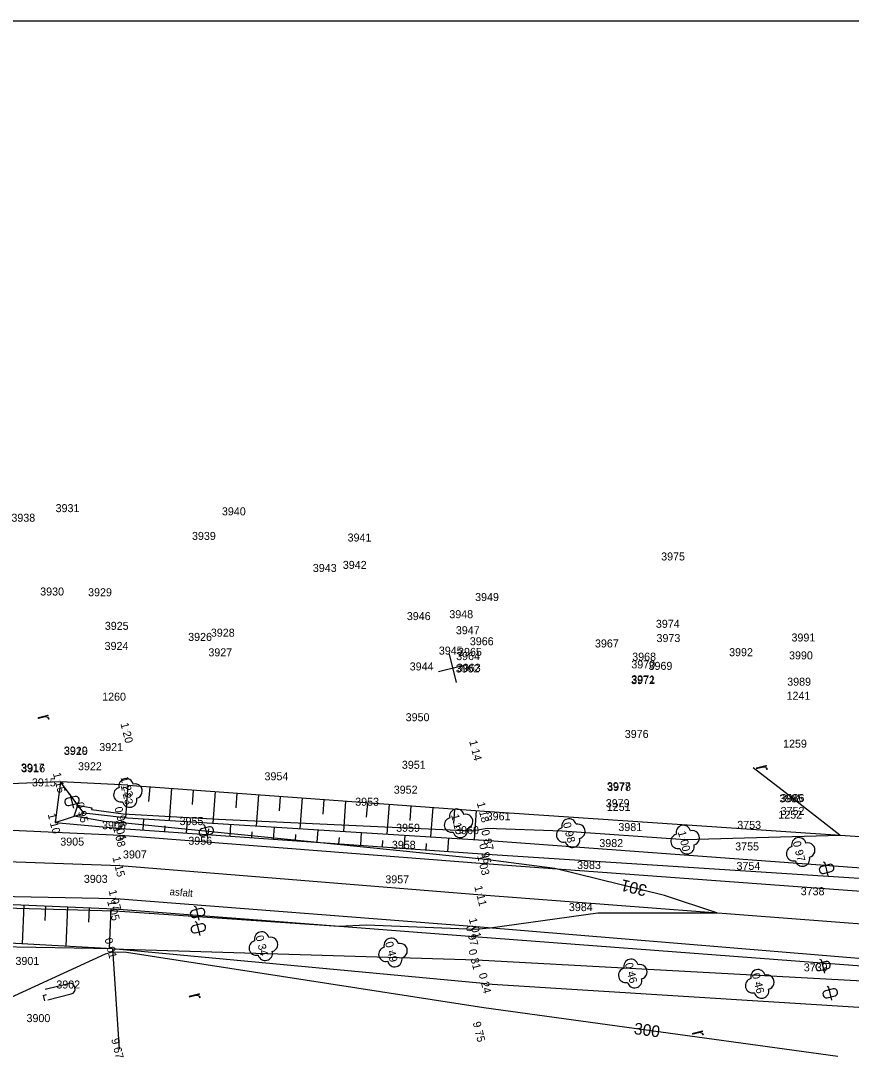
# Model space of a CAD drawing. Extents: x -740053 to -737517, y -1033516 to -1032488.
# Drawn here: x -739360.1 to -739303, y -1032577.7 to -1032506.5 of the extents above; entities that cross this region are included whole.
import ezdxf

# ---------------------------------------------------------------- set-up
doc = ezdxf.new("R2010")
doc.units = 0
for name, color, linetype in [('bod-cislo', 7, 'Continuous'), ('bod-oznac', 7, 'Continuous'), ('bod-vyska', 7, 'Continuous'), ('bod-vyska100', 7, 'Continuous'), ('Contours', 7, 'Continuous'), ('Contours highlighted', 7, 'Continuous'), ('Contours text', 7, 'Continuous'), ('ctv-sit', 7, 'Continuous'), ('Hranice-zelene', 7, 'Continuous'), ('nazvy-bud-povr', 7, 'Continuous'), ('osa-komunikace', 7, 'Continuous'), ('Predmety bez rozlišeni', 7, 'Continuous'), ('silnice', 7, 'Continuous'), ('Technické šrafy', 7, 'Continuous'), ('Terenni-hrana', 7, 'Continuous'), ('Znacky-kultury', 7, 'Continuous')]:
    doc.layers.add(name, color=color, linetype=linetype)

# ---------------------------------------------------------------- blocks, each defined once
blk = doc.blocks.new('POINT_DISPLAY')
blk.add_line((0, 0), (0, 0))
blk = doc.blocks.new('p_strom')
for centre, start, end in [((0, 1), 0, 180), ((-1, 0), 90, 270), ((1, 0), 270, 90), ((0, -1), 180, 0)]:
    blk.add_arc(centre, 1, start, end)
at = {"rotation": -180}
blk.add_blockref('POINT_DISPLAY', (0, 0), dxfattribs=at)
blk = doc.blocks.new('p_orna')
blk.add_text('r', height=2).set_placement((0, 0))
blk = doc.blocks.new('p_leslis')
for p, q in [((-0.05, 4.51), (0.05, 4.51)), ((-0.75, 0.5), (-0.75, 3.81)), ((0.75, 0.5), (0.75, 3.81)), ((0, 0), (0, 0.5)), ((0, 0), (0.75, 0))]:
    blk.add_line(p, q)
for centre, start, end in [((-0.05, 3.81), 90, 180), ((0.05, 3.81), 0, 90)]:
    blk.add_arc(centre, 0.7, start, end)
blk = doc.blocks.new('p_neplod')
for p, q in [((-0.82, 0), (-0.99, -0.18)), ((1, 0), (-0.82, 0)), ((-0.49, 0.56), (-0.49, -0.55)), ((0.05, 1.01), (-0.04, 1.01)), ((0.5, -0.55), (0.5, 0.56)), ((-0.04, -1), (0.05, -1))]:
    blk.add_line(p, q)
for centre, start, end in [((-0.04, 0.56), 90, 180), ((0.05, 0.56), 0, 90), ((-0.04, -0.55), 180, 270), ((0.05, -0.55), 270, 0)]:
    blk.add_arc(centre, 0.45, start, end)
blk = doc.blocks.new('ctvsit')
for p, q in [((0, -2), (0, 2)), ((2, 0), (-2, 0))]:
    blk.add_line(p, q)

msp = doc.modelspace()

# ---------------------------------------------------------------- linework, layer by layer
at = {"layer": 'Contours'}
msp.add_lwpolyline([(-739362.052, -1032567.418), (-739353.659, -1032567.65), (-739352.931, -1032567.699), (-739338.222, -1032568.7), (-739336.341, -1032568.627), (-739328.835, -1032568.904), (-739327.885, -1032568.825), (-739327.83, -1032568.815), (-739320.436, -1032567.79), (-739312.26, -1032567.79), (-739315.844, -1032566.595), (-739323.386, -1032564.753), (-739328.151, -1032564.126), (-739340.621, -1032562.877), (-739353.152, -1032561.618), (-739354.333, -1032561.52), (-739356.417, -1032561.151), (-739356.164, -1032560.396), (-739355.201, -1032560.581), (-739355.221, -1032560.688), (-739353.059, -1032560.997), (-739346.513, -1032561.359), (-739329.091, -1032562.156), (-739328.043, -1032561.983), (-739322.887, -1032562.165), (-739314.427, -1032562.758), (-739303.794, -1032562.445), (-739307.763, -1032559.369), (-739309.748, -1032557.831)], dxfattribs=at)
at = {"layer": 'Contours highlighted'}
msp.add_lwpolyline([(-739403.299, -1032570.496), (-739400.56, -1032570.2), (-739399.624, -1032570.099), (-739390.755, -1032569.573), (-739383.351, -1032569.14), (-739380.871, -1032569.427), (-739380.305, -1032569.493), (-739366.512, -1032571.086), (-739362.044, -1032573.97), (-739361.961, -1032574.147), (-739354.274, -1032570.607), (-739353.782, -1032570.469), (-739352.822, -1032570.487), (-739328.276, -1032574.302), (-739303.936, -1032577.649)], dxfattribs=at)
at = {"layer": 'Hranice-zelene'}
for q in [(-739363.363, -1032570.111), (-739353.338, -1032577.163)]:
    msp.add_line((-739353.795, -1032570.266), q, dxfattribs=at)
at = {"layer": 'osa-komunikace'}
for p, q in [((-739362.629, -1032564.22), (-739353.276, -1032564.547)), ((-739353.276, -1032564.547), (-739328.403, -1032566.555)), ((-739328.403, -1032566.555), (-739297.585, -1032568.913))]:
    msp.add_line(p, q, dxfattribs=at)
at = {"layer": 'Predmety bez rozlišeni'}
for p, q in [((-739409.249, -1032506.478), (-739304.249, -1032506.478)), ((-739304.249, -1032506.478), (-739199.249, -1032506.478))]:
    msp.add_line(p, q, dxfattribs=at)
at = {"layer": 'silnice'}
for p, q in [((-739362.196, -1032562.049), (-739353.246, -1032562.456)), ((-739353.246, -1032562.456), (-739328.225, -1032564.396)), ((-739328.225, -1032564.396), (-739297.577, -1032566.653)), ((-739362.816, -1032566.629), (-739353.554, -1032566.803)), ((-739353.554, -1032566.803), (-739328.793, -1032568.736)), ((-739328.793, -1032568.736), (-739297.981, -1032571.271))]:
    msp.add_line(p, q, dxfattribs=at)
at = {"layer": 'Technické šrafy'}
for p, q in [((-739352.727, -1032559.026), (-739352.89, -1032561.262)), ((-739351.231, -1032559.134), (-739351.304, -1032560.132)), ((-739349.735, -1032559.243), (-739349.896, -1032561.45)), ((-739348.239, -1032559.352), (-739348.312, -1032560.35)), ((-739346.743, -1032559.461), (-739346.902, -1032561.638)), ((-739345.247, -1032559.57), (-739345.32, -1032560.568)), ((-739343.751, -1032559.679), (-739343.907, -1032561.826)), ((-739342.255, -1032559.788), (-739342.328, -1032560.785)), ((-739340.759, -1032559.897), (-739340.913, -1032562.014)), ((-739339.263, -1032560.006), (-739339.336, -1032561.003)), ((-739337.767, -1032560.115), (-739337.919, -1032562.203)), ((-739336.271, -1032560.224), (-739336.344, -1032561.221)), ((-739334.775, -1032560.333), (-739334.925, -1032562.391)), ((-739333.279, -1032560.442), (-739333.351, -1032561.439)), ((-739331.783, -1032560.551), (-739331.93, -1032562.579)), ((-739330.287, -1032560.66), (-739330.359, -1032561.657)), ((-739328.791, -1032560.768), (-739328.936, -1032562.767)), ((-739351.692, -1032562.093), (-739351.639, -1032561.341)), ((-739350.196, -1032562.199), (-739350.169, -1032561.817)), ((-739348.699, -1032562.305), (-739348.644, -1032561.529)), ((-739345.707, -1032562.517), (-739345.65, -1032561.717)), ((-739342.714, -1032562.728), (-739342.656, -1032561.905)), ((-739347.203, -1032562.411), (-739347.175, -1032562.017)), ((-739344.211, -1032562.623), (-739344.182, -1032562.217)), ((-739341.218, -1032562.834), (-739341.189, -1032562.417)), ((-739339.722, -1032562.94), (-739339.662, -1032562.093)), ((-739338.226, -1032563.046), (-739338.195, -1032562.617)), ((-739336.729, -1032563.152), (-739336.668, -1032562.281)), ((-739333.737, -1032563.363), (-739333.673, -1032562.469)), ((-739330.744, -1032563.575), (-739330.679, -1032562.657)), ((-739335.233, -1032563.258), (-739335.202, -1032562.816)), ((-739332.24, -1032563.469), (-739332.208, -1032563.016)), ((-739359.889, -1032567.257), (-739360.001, -1032569.93)), ((-739358.39, -1032567.319), (-739358.432, -1032568.319)), ((-739356.891, -1032567.382), (-739357.005, -1032570.093)), ((-739355.393, -1032567.445), (-739355.435, -1032568.444)), ((-739353.894, -1032567.508), (-739354.009, -1032570.255))]:
    msp.add_line(p, q, dxfattribs=at)
at = {"layer": 'Terenni-hrana'}
for p, q in [((-739357.367, -1032558.781), (-739361.391, -1032558.938)), ((-739357.367, -1032558.781), (-739357.724, -1032561.583)), ((-739355.763, -1032560.934), (-739357.367, -1032558.781)), ((-739352.727, -1032559.026), (-739357.367, -1032558.781)), ((-739352.727, -1032559.026), (-739328.231, -1032560.809)), ((-739357.724, -1032561.583), (-739355.763, -1032560.934)), ((-739353.117, -1032561.248), (-739355.763, -1032560.934)), ((-739353.117, -1032561.248), (-739327.907, -1032562.831)), ((-739328.231, -1032560.809), (-739297.006, -1032562.9)), ((-739357.724, -1032561.583), (-739353.188, -1032561.988)), ((-739353.188, -1032561.988), (-739328.054, -1032563.765)), ((-739327.907, -1032562.831), (-739298.411, -1032564.976)), ((-739328.054, -1032563.765), (-739297.224, -1032565.759)), ((-739362.886, -1032567.131), (-739353.652, -1032567.518)), ((-739353.652, -1032567.518), (-739328.964, -1032569.408)), ((-739353.795, -1032570.266), (-739363.403, -1032569.746)), ((-739328.964, -1032569.408), (-739297.949, -1032571.768)), ((-739353.795, -1032570.266), (-739328.781, -1032571.033)), ((-739328.071, -1032572.669), (-739353.795, -1032570.266)), ((-739328.781, -1032571.033), (-739297.95, -1032572.707)), ((-739328.071, -1032572.669), (-739298.478, -1032574.541))]:
    msp.add_line(p, q, dxfattribs=at)

# ---------------------------------------------------------------- block references
at = {"layer": 'bod-oznac', "rotation": -75.86979040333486}
for p in [(-739352.733, -1032555.315), (-739328.754, -1032556.558), (-739357.367, -1032558.781), (-739352.727, -1032559.026), (-739352.729, -1032559.552), (-739355.763, -1032560.934), (-739353.117, -1032561.248), (-739328.231, -1032560.809), (-739357.724, -1032561.583), (-739353.188, -1032561.988), (-739330.002, -1032561.637), (-739353.246, -1032562.456), (-739322.293, -1032562.315), (-739327.907, -1032562.831), (-739314.427, -1032562.758), (-739328.054, -1032563.765), (-739306.49, -1032563.606), (-739353.276, -1032564.547), (-739328.225, -1032564.396), (-739353.554, -1032566.803), (-739328.403, -1032566.555), (-739353.652, -1032567.518), (-739328.793, -1032568.736), (-739328.964, -1032569.408), (-739353.795, -1032570.266), (-739343.415, -1032570.087), (-739334.511, -1032570.516), (-739328.781, -1032571.033), (-739318.028, -1032571.966), (-739328.071, -1032572.669), (-739309.301, -1032572.677), (-739328.49, -1032576.002), (-739353.338, -1032577.163)]:
    msp.add_blockref('POINT_DISPLAY', p, dxfattribs=at)
at = {"layer": 'ctv-sit', "xscale": 0.49999999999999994, "yscale": 0.5, "rotation": 104.13020959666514}
msp.add_blockref('ctvsit', (-739330.403, -1032550.993), dxfattribs=at)
at = {"layer": 'Znacky-kultury', "xscale": 0.49999999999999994}
for name, p, yscale, rotation in [('p_orna', (-739358.967, -1032554.268), 0.5, -75.86979040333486), ('p_orna', (-739309.596, -1032557.725), 0.5, -75.86979040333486), ('p_strom', (-739352.729, -1032559.552), 0.4999999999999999, -75.86979040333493), ('p_neplod', (-739356.574, -1032560.104), 0.5, -75.86979040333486), ('p_strom', (-739330.002, -1032561.637), 0.4999999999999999, -75.86979040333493), ('p_strom', (-739322.293, -1032562.315), 0.4999999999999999, -75.86979040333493), ('p_neplod', (-739347.344, -1032562.194), 0.5, -75.86979040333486), ('p_strom', (-739314.427, -1032562.758), 0.4999999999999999, -75.86979040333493), ('p_strom', (-739306.49, -1032563.606), 0.4999999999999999, -75.86979040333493), ('p_neplod', (-739304.715, -1032564.769), 0.5, -75.86979040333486), ('p_neplod', (-739347.946, -1032567.805), 0.5, -75.86979040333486), ('p_neplod', (-739347.892, -1032568.859), 0.5, -75.86979040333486), ('p_strom', (-739343.415, -1032570.087), 0.4999999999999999, -75.86979040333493), ('p_strom', (-739334.511, -1032570.516), 0.4999999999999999, -75.86979040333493), ('p_strom', (-739318.028, -1032571.966), 0.4999999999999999, -75.86979040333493), ('p_neplod', (-739304.957, -1032571.452), 0.5, -75.86979040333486), ('p_strom', (-739309.301, -1032572.677), 0.4999999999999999, -75.86979040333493), ('p_leslis', (-739358.562, -1032573.47), 0.5, -75.86979040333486), ('p_orna', (-739348.573, -1032573.414), 0.5, -75.86979040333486), ('p_neplod', (-739304.461, -1032573.321), 0.5, -75.86979040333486), ('p_orna', (-739313.993, -1032575.971), 0.5, -75.86979040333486)]:
    msp.add_blockref(name, p, dxfattribs=dict(at, yscale=yscale, rotation=rotation))

# ---------------------------------------------------------------- texts
at = {"layer": 'bod-cislo'}
for s, p in [('3931', (-739357.699, -1032540.253)), ('3940', (-739346.268, -1032540.473)), ('3938', (-739360.738, -1032540.913)), ('3939', (-739348.325, -1032542.163)), ('3941', (-739337.629, -1032542.273)), ('3975', (-739316.078, -1032543.573)), ('3943', (-739340.018, -1032544.363)), ('3942', (-739337.958, -1032544.153)), ('3930', (-739358.758, -1032545.983)), ('3929', (-739355.465, -1032546.033)), ('3949', (-739328.865, -1032546.363)), ('3948', (-739330.638, -1032547.543)), ('3946', (-739333.558, -1032547.673)), ('3974', (-739316.441, -1032548.203)), ('3925', (-739354.318, -1032548.343)), ('3928', (-739347.028, -1032548.813)), ('3947', (-739330.188, -1032548.643)), ('3924', (-739354.331, -1032549.723)), ('3926', (-739348.588, -1032549.103)), ('3966', (-739329.228, -1032549.403)), ('3967', (-739320.628, -1032549.553)), ('3973', (-739316.398, -1032549.183)), ('3991', (-739307.119, -1032549.143)), ('3927', (-739347.198, -1032550.163)), ('3945', (-739331.358, -1032550.043)), ('3964', (-739330.171, -1032550.423)), ('3965', (-739330.038, -1032550.133)), ('3992', (-739311.408, -1032550.153)), ('3990', (-739307.288, -1032550.373)), ('3944', (-739333.361, -1032551.133)), ('3970', (-739318.128, -1032550.993)), ('3968', (-739318.068, -1032550.463)), ('3969', (-739316.945, -1032551.093)), ('3962', (-739330.198, -1032551.273)), ('3963', (-739330.118, -1032551.223)), ('3972', (-739318.148, -1032552.073)), ('3971', (-739318.129, -1032552.013)), ('3989', (-739307.415, -1032552.183)), ('1260', (-739354.5, -1032553.212)), ('1241', (-739307.46, -1032553.148)), ('3950', (-739333.638, -1032554.623)), ('3976', (-739318.578, -1032555.773)), ('3921', (-739354.699, -1032556.673)), ('1259', (-739307.698, -1032556.44)), ('3920', (-739357.128, -1032556.943)), ('3919', (-739357.125, -1032556.913)), ('3917', (-739360.088, -1032558.083)), ('3916', (-739360.058, -1032558.133)), ('3922', (-739356.158, -1032557.993)), ('3951', (-739333.899, -1032557.893)), ('3954', (-739343.341, -1032558.683)), ('3915', (-739359.328, -1032559.103)), ('3952', (-739334.458, -1032559.603)), ('3977', (-739319.808, -1032559.363)), ('3978', (-739319.788, -1032559.413)), ('3985', (-739307.958, -1032560.203)), ('3986', (-739307.868, -1032560.173)), ('3953', (-739337.108, -1032560.433)), ('3979', (-739319.885, -1032560.533)), ('1251', (-739319.818, -1032560.788)), ('3752', (-739307.868, -1032561.063)), ('3955', (-739349.178, -1032561.763)), ('3961', (-739328.069, -1032561.433)), ('1252', (-739308.028, -1032561.323)), ('3906', (-739354.508, -1032562.043)), ('3959', (-739334.295, -1032562.223)), ('3960', (-739330.238, -1032562.383)), ('3981', (-739319.019, -1032562.173)), ('3753', (-739310.848, -1032562.023)), ('3905', (-739357.378, -1032563.173)), ('3956', (-739348.578, -1032563.113)), ('3982', (-739320.328, -1032563.273)), ('3958', (-739334.588, -1032563.393)), ('3755', (-739310.988, -1032563.503)), ('3907', (-739353.068, -1032564.053)), ('3983', (-739321.858, -1032564.783)), ('3754', (-739310.901, -1032564.843)), ('3903', (-739355.758, -1032565.733)), ('3957', (-739335.038, -1032565.763)), ('3738', (-739306.488, -1032566.583)), ('3984', (-739322.421, -1032567.673)), ('3901', (-739360.459, -1032571.373)), ('3739', (-739306.275, -1032571.813)), ('3902', (-739357.648, -1032572.993)), ('3900', (-739359.698, -1032575.303))]:
    msp.add_text(s, height=0.55, dxfattribs=at).set_placement(p)
at = {"layer": 'bod-vyska'}
for s, p in [('1 20', (-739353.243, -1032554.792)), ('1 14', (-739329.274, -1032555.997)), ('1 15', (-739357.887, -1032558.22)), ('1 23', (-739353.239, -1032559.029)), ('1 22', (-739353.237, -1032558.502)), ('0 95', (-739356.311, -1032560.259)), ('0 96', (-739353.665, -1032560.572)), ('1 18', (-739328.75, -1032560.248)), ('1 10', (-739358.244, -1032561.021)), ('1 10', (-739330.522, -1032561.075)), ('1 08', (-739353.755, -1032561.933)), ('1 04', (-739353.698, -1032561.464)), ('0 98', (-739322.842, -1032561.64)), ('0 87', (-739328.455, -1032562.156)), ('1 00', (-739314.937, -1032562.235)), ('0 96', (-739328.602, -1032563.09)), ('0 97', (-739307.038, -1032562.931)), ('1 15', (-739353.796, -1032563.985)), ('1 03', (-739328.735, -1032563.873)), ('1 07', (-739354.064, -1032566.279)), ('1 11', (-739328.923, -1032565.994)), ('1 05', (-739354.162, -1032566.995)), ('1 01', (-739329.302, -1032568.213)), ('0 97', (-739329.512, -1032568.733)), ('0 01', (-739354.344, -1032569.591)), ('0 34', (-739343.963, -1032569.411)), ('0 49', (-739335.059, -1032569.841)), ('0 31', (-739329.33, -1032570.357)), ('0 46', (-739318.577, -1032571.291)), ('0 24', (-739328.619, -1032571.993)), ('0 46', (-739309.849, -1032572.001)), ('9 75', (-739329.035, -1032575.339)), ('9 67', (-739353.886, -1032576.488))]:
    msp.add_text(s, height=0.55, rotation=284.13021, dxfattribs=at).set_placement(p)
at = {"layer": 'bod-vyska100'}
for s, p in [('301 20', (-739352.805, -1032555.168)), ('301 14', (-739328.826, -1032556.408)), ('301 15', (-739357.44, -1032558.631)), ('301 22', (-739352.799, -1032558.879)), ('301 23', (-739352.8, -1032559.405)), ('300 95', (-739355.836, -1032560.781)), ('300 96', (-739353.19, -1032561.094)), ('301 18', (-739328.303, -1032560.659)), ('301 10', (-739357.796, -1032561.432)), ('301 04', (-739353.259, -1032561.841)), ('301 10', (-739330.074, -1032561.486)), ('301 08', (-739353.317, -1032562.309)), ('300 87', (-739327.98, -1032562.678)), ('300 98', (-739322.366, -1032562.162)), ('301 00', (-739314.499, -1032562.612)), ('300 96', (-739328.127, -1032563.612)), ('300 97', (-739306.563, -1032563.453)), ('301 15', (-739353.348, -1032564.396)), ('301 03', (-739328.296, -1032564.249)), ('301 07', (-739353.625, -1032566.656)), ('301 11', (-739328.475, -1032566.405)), ('301 05', (-739353.723, -1032567.371)), ('301 01', (-739328.864, -1032568.589)), ('300 97', (-739329.037, -1032569.255)), ('300 01', (-739353.869, -1032570.113)), ('300 34', (-739343.488, -1032569.933)), ('300 49', (-739334.584, -1032570.362)), ('300 31', (-739328.855, -1032570.879)), ('300 46', (-739318.101, -1032571.812)), ('300 24', (-739328.144, -1032572.515)), ('300 46', (-739309.374, -1032572.523)), ('299 75', (-739328.562, -1032575.849)), ('299 67', (-739353.411, -1032577.01))]:
    msp.add_text(s, height=0.05, rotation=284.13021, dxfattribs=at).set_placement(p)
at = {"layer": 'Contours text'}
for s, rotation, p in [('301', 166.27207, (-739316.996, -1032565.902)), ('300', 352.16803, (-739317.987, -1032576.121))]:
    msp.add_text(s, height=0.8, rotation=rotation, dxfattribs=at).set_placement(p)
at = {"layer": 'nazvy-bud-povr'}
msp.add_text('asfalt', height=0.5, rotation=354.91633, dxfattribs=at).set_placement((-739349.882, -1032566.57))

doc.saveas('drawing.dxf')
